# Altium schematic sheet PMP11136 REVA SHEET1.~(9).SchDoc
size 431 x 279 mm; Date: Not shown in title block; ApprovedBy: Not shown in title block; CheckedBy: Not shown in title block; Author: Not shown in title block; CompanyName: Not shown in title block; Engineer: Not shown in title block; Organization: Not shown in title block; Address1: Not shown in title block; Address2: Not shown in title block; Address3: Not shown in title block; Address4: Not shown in title block; DocumentNumber: 1; Revision: Use project parameter SCH_Rev; SheetNumber: 1; SheetTotal: 3; PageSetup: Record=PageOptions¦CenterHorizontal=True¦CenterVertical=True¦PrintScale=1.00¦XCorrection=1.00¦YCorrection=1.00¦PrintKind=0¦BorderSize=5000000¦LeftOffset=0¦BottomOffset=0¦Orientation=2¦PaperLength=1000¦PaperWidth=1000¦Scale=100¦PaperSource=15¦PrintQuality=600¦MediaType=1¦DitherType=10¦PaperKind=Letter¦PrintScaleMode=1
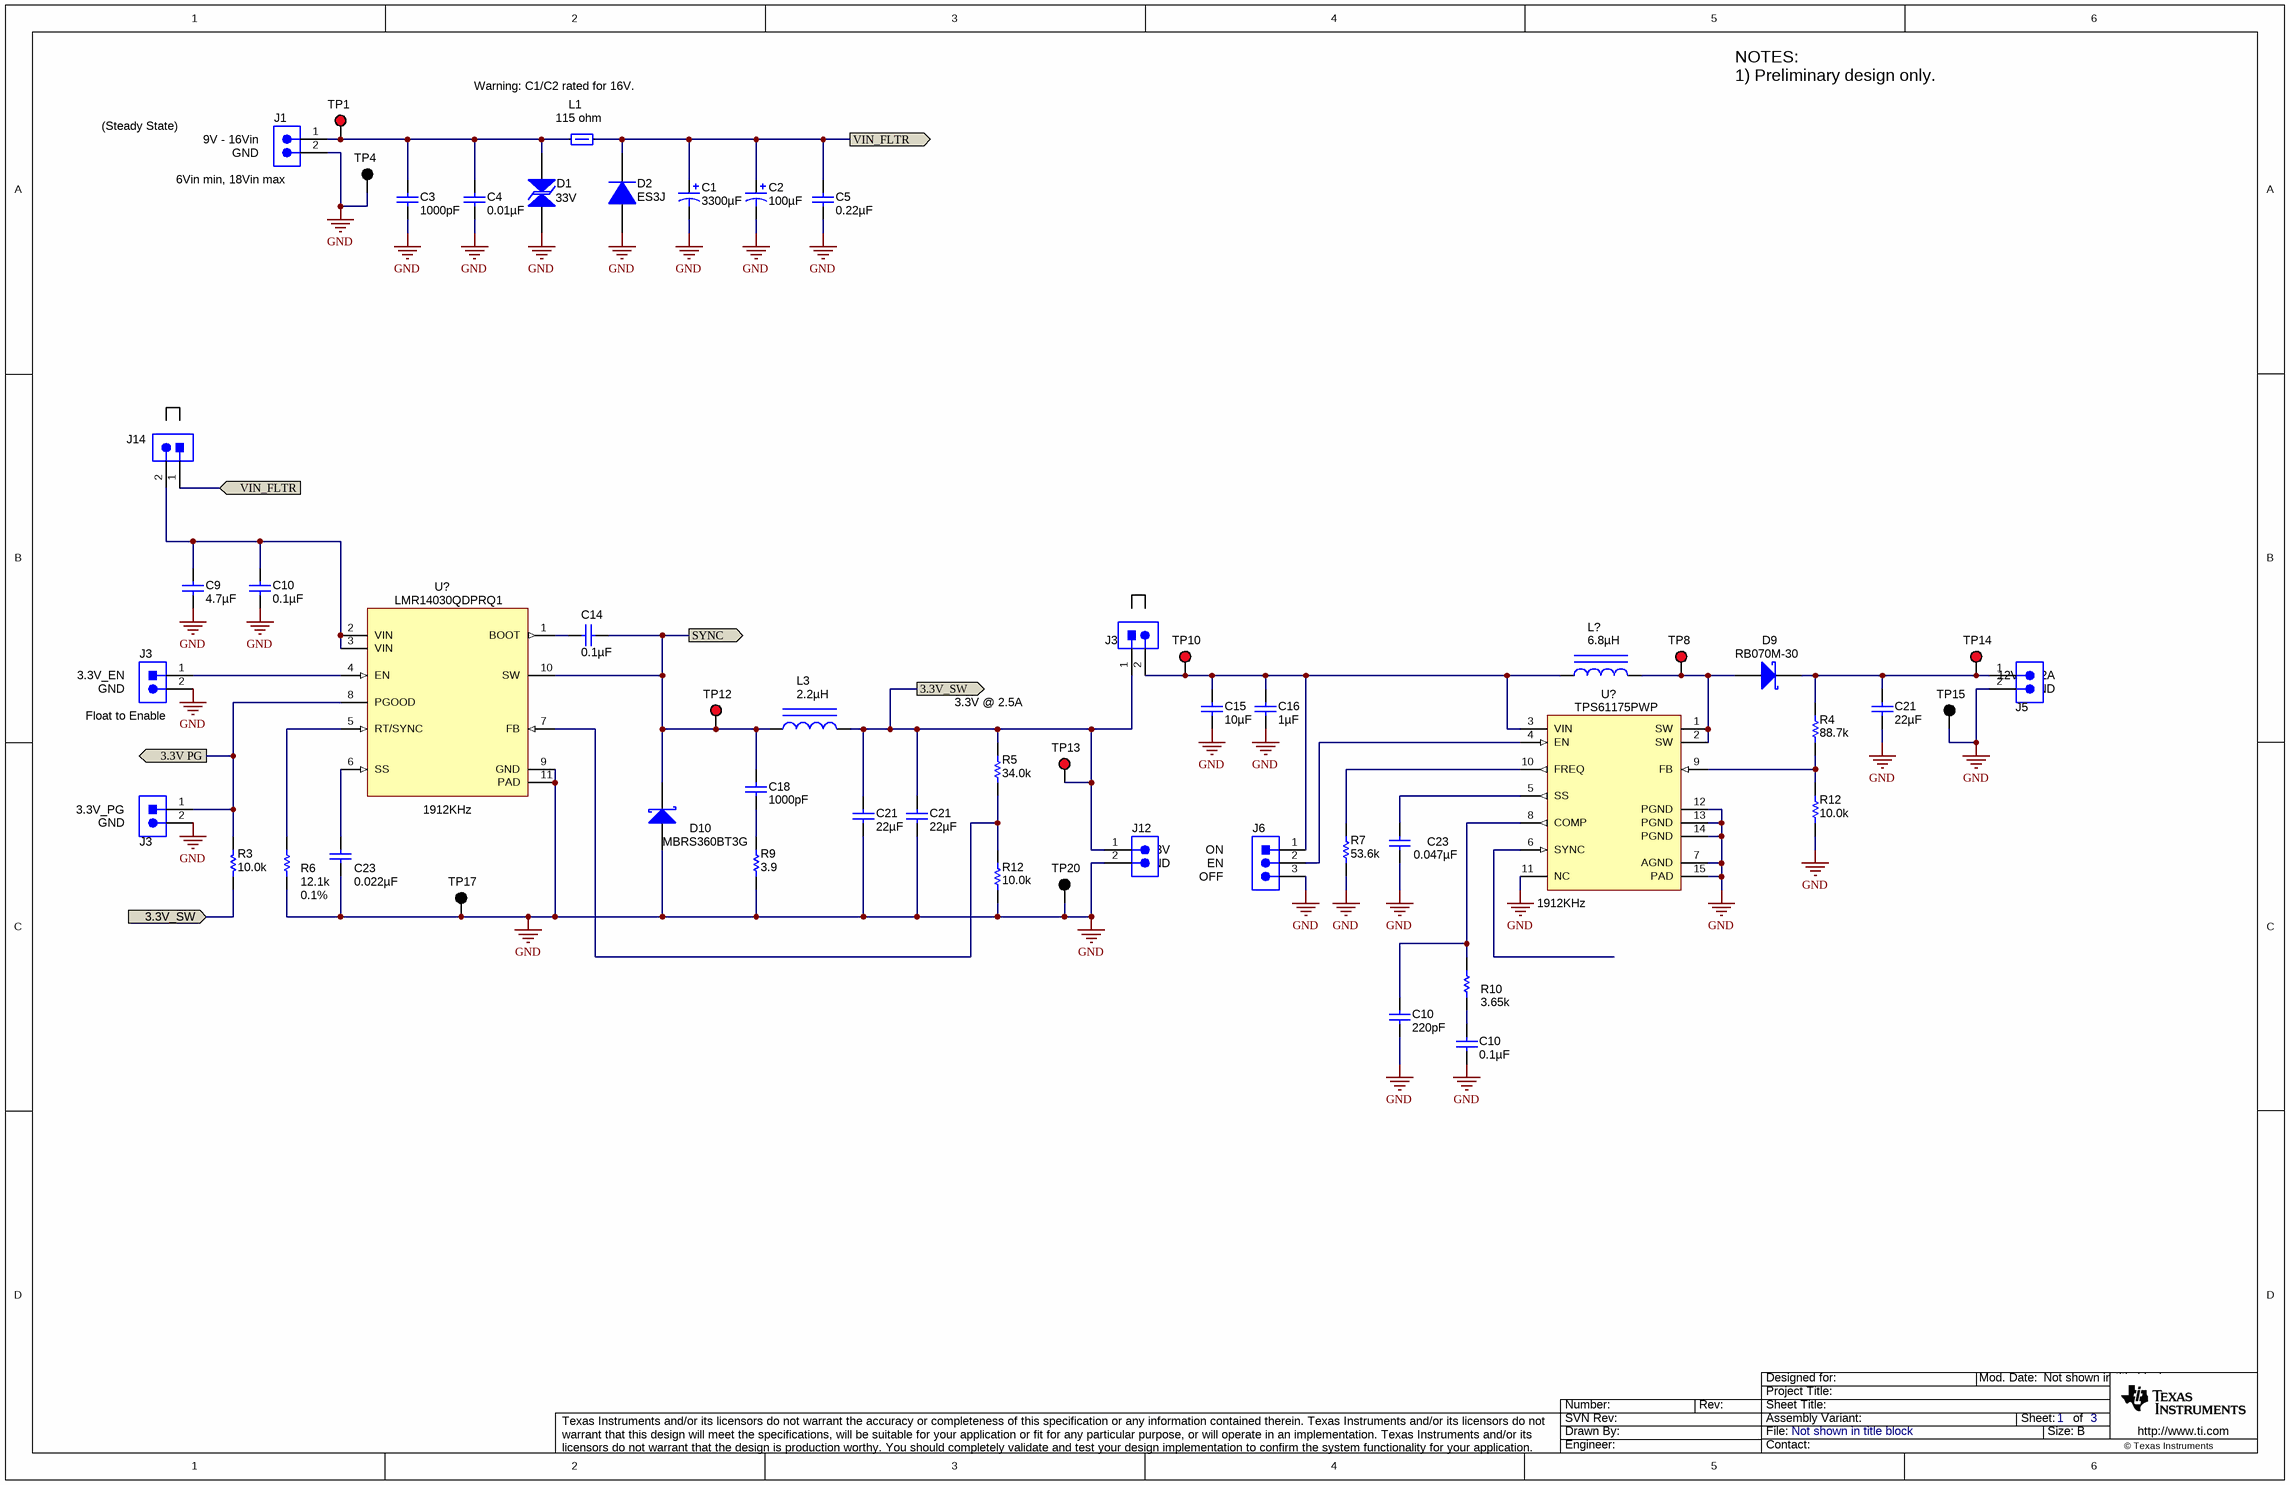
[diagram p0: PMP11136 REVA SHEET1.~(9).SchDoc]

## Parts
(Parts that share a designator on the sheet are numbered #1, #2 ... from top to bottom, then left to right.)
C1  ValueDisplayed: 3300µF  [SM_RADIAL_J16]  (hidden comment: EEV-FK1C332M)
C2  ValueDisplayed: 100µF  [SM_RADIAL_D]  (hidden comment: EEE-FK1C101P)
C3  ValueDisplayed: 1000pF  [0603]  (hidden comment: C1608C0G2A102J)
C4  ValueDisplayed: 0.01µF  [0603]  (hidden comment: C1608X7R2A103K)
C5  ValueDisplayed: 0.22µF  [0603]  (hidden comment: C1608X7R1H224K080AB)
C9  ValueDisplayed: 4.7µF  [1210]  (hidden comment: C3225X7R1H475M250AB)
C10#1  ValueDisplayed: 0.1µF  [0603]  (hidden comment: C1608X7R1H104K)
C10#2  ValueDisplayed: 220pF  [0603]  (hidden comment: C1608X7R1H221K)
C10#3  ValueDisplayed: 0.1µF  [0603]  (hidden comment: C1608X7R1H104K)
C14  ValueDisplayed: 0.1µF  [0603]  (hidden comment: C1608X7R1H104K)
C15  ValueDisplayed: 10µF  [0805]  (hidden comment: GRM21BR71A106KE51L)
C16  ValueDisplayed: 1µF  [0603]  (hidden comment: C1608X7R1E105K)
C18  ValueDisplayed: 1000pF  [0603]  (hidden comment: C1608C0G2A102J)
C21#1  ValueDisplayed: 22µF  [1210]  (hidden comment: C3225X7R1C226M250AC)
C21#2  ValueDisplayed: 22µF  [1210]  (hidden comment: C3225X7R1C226M250AC)
C21#3  ValueDisplayed: 22µF  [1210]  (hidden comment: C3225X7R1C226M250AC)
C23#1  ValueDisplayed: 0.047µF  [0603]  (hidden comment: C1608X7R1H473K)
C23#2  ValueDisplayed: 0.022µF  [0603]  (hidden comment: C1608X7R1H223K)
D1  value 33V  [DO-214AB-Bi]  (hidden comment: 1.5SMC33CA-E3/57T)
D2  ES3J  [SMC]
D9  RB070M-30  [SOD-123]
D10  MBRS360BT3G  [SMB]
J1  ED555/2DS  [TERM_BLK_ED555-2DS]  (value not drawn)
J3#1  PEC02SAAN  [CONN_PEC02SAAN]  (value not drawn)
J3#2  PEC02SAAN  [CONN_PEC02SAAN]  (value not drawn)
J3#3  PEC02SAAN  [CONN_PEC02SAAN]  (value not drawn)
J5  ED555/2DS  [TERM_BLK_ED555-2DS]  (value not drawn)
J6  PEC03SAAN  [CONN_PEC03SAAN]  (value not drawn)
J12  ED555/2DS  [TERM_BLK_ED555-2DS]  (value not drawn)
J14  PEC02SAAN  [CONN_PEC02SAAN]  (value not drawn)
L1  value 115 ohm  [28F0181]  (hidden comment: 28F0181-1SR-10)
L3  ValueDisplayed: 2.2µH  [SDR7045]  (hidden comment: SLF6045T-2R2N3R3-3PF)
L?  ValueDisplayed: 6.8µH  [VLF504015MT]  (hidden comment: VLF504015MT-6R8M)
R3  ValueDisplayed: 10.0k  [0603]  (hidden comment: CRCW060310K0FKEA)
R4  ValueDisplayed: 88.7k  [0603]  (hidden comment: CRCW060388K7FKEA)
R5  ValueDisplayed: 34.0k  [0603]  (hidden comment: CRCW060334K0FKEA)
R6  Value1: 0.1%  ValueDisplayed: 12.1k  [0603]
R7  ValueDisplayed: 53.6k  [0603]  (hidden comment: CRCW060353K6FKEA)
R9  value 3.9  [2010]  (hidden comment: CRCW20103R90JNEF)
R10  ValueDisplayed: 3.65k  [0603]  (hidden comment: CRCW06033K65FKEA)
R12#1  ValueDisplayed: 10.0k  [0603]  (hidden comment: CRCW060310K0FKEA)
R12#2  ValueDisplayed: 10.0k  [0603]  (hidden comment: CRCW060310K0FKEA)
TP1  5000  [Keystone5000]  (value not drawn)
TP4  5001  [Keystone5001]  (value not drawn)
TP8  5000  [Keystone5000]  (value not drawn)
TP10  5000  [Keystone5000]  (value not drawn)
TP12  5000  [Keystone5000]  (value not drawn)
TP13  5000  [Keystone5000]  (value not drawn)
TP14  5000  [Keystone5000]  (value not drawn)
TP15  5001  [Keystone5001]  (value not drawn)
TP17  5001  [Keystone5001]  (value not drawn)
TP20  5001  [Keystone5001]  (value not drawn)
U?#1  LMR14030QDPRQ1  [DPR0010A]
U?#2  TPS61175PWP  [PWP0014E_N]

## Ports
3.3V PG, 3.3V_SW, SYNC, VIN_FLTR

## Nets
GND: C1.2(-) C2.2(-) C3.2 C4.2 C5.2 C9.1 C10#1.2 C10#2.2 C10#3.2 C15.2 C16.2 C21#1.2 C21#2.2 C21#3.2 C23#1.2 C23#2.2 D1.1 D2.2(A) D10.2(A) J1.2 J3#2.2 J3#3.2 J5.2 J6.3 J12.2 R6.1 R7.1 R9.1 R12#1.1 R12#2.1 TP4.1 TP15.1 TP17.1 TP20.1 U?#1.9(GND) U?#1.11(PAD) U?#2.7(AGND) U?#2.11(NC) U?#2.12(PGND) U?#2.13(PGND) U?#2.14(PGND) U?#2.15(PAD)
3.3V PG: J3#3.1 R3.2 U?#1.8(PGOOD) ; port 3.3V PG
3.3V_SW: C21#2.1 C21#3.1 J3#1.1 J12.1 L3.2 R3.1 R5.2 TP13.1 ; port 3.3V_SW
SYNC: C14.2 C18.1 D10.1(K) L3.1 TP12.1 U?#1.10(SW) ; port SYNC
VIN_FLTR: C1.1(+) C2.1(+) C5.1 D2.1(K) J14.1 L1.2 ; port VIN_FLTR
NetC3_1: C3.1 C4.1 D1.2 J1.1 L1.1 TP1.1
NetC9_2: C9.2 C10#1.1 J14.2 U?#1.2(VIN) U?#1.3(VIN)
NetC10#2_1: C10#2.1 R10.2 U?#2.8(COMP)
NetC10#3_1: C10#3.1 R10.1
NetC14_1: C14.1 U?#1.1(BOOT)
NetC15_1: C15.1 C16.1 J3#1.2 J6.1 L?.1 TP10.1 U?#2.3(VIN)
NetC18_2: C18.2 R9.2
NetC21#1_1: C21#1.1 D9.1(K) J5.1 R4.2 TP14.1
NetC23#1_1: C23#1.1 U?#2.5(SS)
NetC23#2_1: C23#2.1 U?#1.6(SS)
NetD9_2: D9.2(A) L?.2 TP8.1 U?#2.1(SW) U?#2.2(SW)
NetJ3#2_1: J3#2.1 U?#1.4(EN)
NetJ6_2: J6.2 U?#2.4(EN)
NetR4_1: R4.1 R12#1.2 U?#2.9(FB)
NetR5_1: R5.1 R12#2.2 U?#1.7(FB)
NetR6_2: R6.2 U?#1.5(RT/SYNC)
NetR7_2: R7.2 U?#2.10(FREQ)

Not connected (* = marked no-connect by the designer): U?#2 6(SYNC)

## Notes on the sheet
- Warning: C1/C2 rated for 16V.
- (near J1) (Steady State)
- (near J1) 9V - 16Vin
- (near J1) GND
- NOTES:
  1) Preliminary design only.
- (near J1) 6Vin min, 18Vin max
- (near J3#2) 3.3V_EN
- (near J3#2) GND
- 3.3V @ 2.5A
- (near J5) 12V@0.2A
- (near J5) GND
- (near J3#2) Float to Enable
- (near J3#3) 3.3V_PG
- (near J3#3) GND
- (near U?#1) 1912KHz
- (near J12) 3.3V
- (near J12) GND
- (near J6) ON
- (near J6) EN
- (near J6) OFF
- (near U?#2) 1912KHz

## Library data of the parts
C1 = EEV-FK1C332M: CAP, AL, 3300 µF, 16 V, +/- 20%, 0.035 ohm, SMD; Manufacturer: Panasonic; Polarized: Y; CompType: Capacitor; Value: 3300uF; U/M: EA; Cap_F: 0.0033; Tolerance_%: 20; VDC_V: 16; Value2: 16V; ESR_ohm: 0.035; IRMS_A: 1.8; TaMin_C: -55; TaMax_C: 105; Cap_Case: J16
C2 = EEE-FK1C101P: CAP, AL, 100 µF, 16 V, +/- 20%, 0.36 ohm, SMD; Manufacturer: Panasonic; Polarized: Y; CompType: Capacitor; Value: 100uF; U/M: EA; Cap_F: 0.0001; Tolerance_%: 20; VDC_V: 16; Value2: 16V; ESR_ohm: 0.36; IRMS_A: 0.24; TaMin_C: -55; TaMax_C: 105; Cap_Case: D
C3 C18 = C1608C0G2A102J: CAP, CERM, 1000 pF, 100 V, +/- 5%, C0G/NP0, 0603; Manufacturer: TDK; Polarized: N; CompType: Capacitor; Value: 1000pF; U/M: EA; Cap_F: 0.000000001; Tolerance_%: 5; ESR_ohm: 0.0589; Value1: 0.0589 ohm; VDC_V: 100; Value2: 100V; TaMin_C: -55; TaMax_C: 125
C4 = C1608X7R2A103K: CAP, CERM, 0.01 µF, 100 V, +/- 10%, X7R, 0603; Manufacturer: TDK; Polarized: N; CompType: Capacitor; Value: 0.01uF; U/M: EA; Cap_F: 0.00000001; Tolerance_%: 10; ESR_ohm: 0.0661; Value1: 0.0661 ohm; VDC_V: 100; Value2: 100V; TaMin_C: -55; TaMax_C: 125
C5 = C1608X7R1H224K080AB: CAP, CERM, 0.22 µF, 50 V, +/- 10%, X7R, 0603; Manufacturer: TDK; Polarized: N; CompType: Capacitor; Value: 0.22uF; U/M: EA; Cap_F: 0.00000022; Tolerance_%: 10; Value1: Unknown; VDC_V: 50; Value2: 50V; TaMin_C: -55; TaMax_C: 125
C9 = C3225X7R1E106M: CAP, CERM, 4.7uF, 50V, +/-20%, X7R, 1210; Manufacturer: TDK; Polarized: N; CompType: Capacitor; U/M: EA; Cap_F: 0.00001; Tolerance_%: 20; ESR_Ohm: 0.0027; Value1: 0.0027 ohm; VDC_V: 50; IRMS_A: 3; TaMin_C: -55; TaMax_C: 125
C10#1 C10#3 C14 = C1608X7R1H104K: CAP, CERM, 0.1uF, 50V, +/-10%, X7R, 0603; Manufacturer: TDK; Polarized: N; CompType: Capacitor; U/M: EA; Cap_F: 0.0000001; Tolerance_%: 10; ESR_Ohm: 0.017; Value1: 0.017 ohm; VDC_V: 50; TaMin_C: -55; TaMax_C: 125
C10#2 = C1608X7R1H221K: CAP, CERM, 220 pF, 50 V, +/- 10%, X7R, 0603; Manufacturer: TDK; Polarized: N; CompType: Capacitor; Value: 220pF; U/M: EA; Cap_F: 0.00000000022; Tolerance_%: 10; Value1: Unknown; VDC_V: 50; Value2: 50V; TaMin_C: -55; TaMax_C: 125
C15 = GRM21BR71A106KE51L: CAP, CERM, 10uF, 10V, +/-10%, X7R, 0805; Manufacturer: MuRata; Polarized: N; CompType: Capacitor; U/M: EA; Cap_F: 0.00001; Tolerance_%: 10; ESR_Ohm: 0.003; Value1: 0.003 ohm; TaMin_C: -55; TaMax_C: 125
C16 = C1608X7R1C105K: CAP, CERM, 1uF, 25V, +/-10%, X7R, 0603; Manufacturer: TDK; Polarized: N; CompType: Capacitor; U/M: EA; Cap_F: 0.000001; Tolerance_%: 10; ESR_Ohm: 0.0057; Value1: 0.0057 ohm; VDC_V: 25; TaMin_C: -55; TaMax_C: 125
C21#1-C21#3 = C3225X7R1C226M: CAP, CERM, 22 µF, 16 V, +/- 20%, X7R, 1210; Manufacturer: TDK; Polarized: N; CompType: Capacitor; Value: 22uF; U/M: EA; Cap_F: 0.000022; Tolerance_%: 20; ESR_ohm: 0.002; Value1: 0.002 ohm; VDC_V: 16; Value2: 16V; IRMS_A: 8.11; TaMin_C: -55; TaMax_C: 125
C23#1 = C1608X7R1H473K: CAP, CERM, 0.047 µF, 50 V, +/- 10%, X7R, 0603; Manufacturer: TDK; Polarized: N; CompType: Capacitor; Value: 0.047uF; U/M: EA; Cap_F: 0.000000047; Tolerance_%: 10; ESR_ohm: 0.0234; Value1: 0.0234 ohm; VDC_V: 50; Value2: 50V; TaMin_C: -55; TaMax_C: 125
C23#2 = C1608X7R1H223K: CAP, CERM, 0.022 µF, 50 V, +/- 10%, X7R, 0603; Manufacturer: TDK; Polarized: N; CompType: Capacitor; Value: 0.022uF; U/M: EA; Cap_F: 0.000000022; Tolerance_%: 10; ESR_ohm: 0.0383; Value1: 0.0383 ohm; VDC_V: 50; Value2: 50V; TaMin_C: -55; TaMax_C: 125
D1 = 1.5SMC33CA-E3/57T: Diode, TVS, Bi, 33V, 1500W, DO-214AB; Manufacturer: Vishay-Dale; U/M: EA; Power_W: 1500; Vr_V: 28.2; RJA_CperW: 75
D2 = ES3D-E3/57T: Diode, Ultrafast, 600V, 3A, SMC; Manufacturer: Fairchild; U/M: EA; Vf_V: 0.9; Value2: 0.9V; Io_A: 3; Vr_V: 600; TJmax_C: 150
D9 = B130LAW-7-F: Diode, Schottky, 30V, 1.5A, SOD-123; Manufacturer: Rohm; U/M: EA; Vf_V: 0.38; Value1: 1A; Value2: 0.38V; Io_A: 1.5; Vr_V: 30; TJmax_C: 125
D10 = MBRS260T3G: Diode, Schottky, 60V, 3A, SMB; Manufacturer: ON Semiconductor; U/M: EA; Vf_V: 0.63; Value2: 0.63V; Io_A: 2; Vr_V: 60; TJmax_C: 125; RJC_CperW: 24
J1 J5 J12 = ED555/2DS: Terminal Block, 6A, 3.5mm Pitch, 2-Pos, TH; Manufacturer: On-Shore Technology, Inc.; SymbolCreator: a0412235; CompType: Connector; U/M: EA
J3#1-J3#3 J14 = PEC02SAAN: Header, 100mil, 2x1, Tin, TH; Manufacturer: Sullins Connector Solutions; SymbolCreator: a0412235; U/M: EA
J6 = PEC03SAAN: Header, 100mil, 3x1, Tin, TH; Manufacturer: Sullins Connector Solutions; SymbolCreator: a0799628; U/M: EA
L1 = 28F0181-1SR-10: Ferrite Bead, 115 ohm @ 100MHz, 10A, SMD, 2-Leads, Body 8.74x4.65mm; Manufacturer: Laird-Signal Integrity Products; Imax_A: 10; DCR_ohm: 0.001; Value1: 0.001 ohm; ZTyp@100MHz_Ohm: 115
L3 = SDR7045-2R2M: Inductor, SMT, 3.3A, 18 milliohm; Manufacturer: TDK; Value: 2.2uH; Ind_H: 2.2E-6; Imax_A: 3.3; DCR_ohm: 0.032; Material: Ferrite
L? = VLF504015MT-6R8M: Inductor, Shielded, Ferrite, 6.8 µH, 1.83 A, 0.08 ohm, SMD; Manufacturer: TDK; Value: 6.8uH; Ind_H: 6.8E-6; Imax_A: 1.83; Irms: 2A @ 40C rise; Isat: 1.83A @ 30% inductance drop; DCR_ohm: 0.08; Value2: 1.83A
R3 R12#1 R12#2 = CRCW060310K0FKEA: RES, 10.0 k, 1%, 0.1 W, 0603; Manufacturer: Vishay-Dale; CompType: Resistor; Value: 10.0k; Res_ohm: 10000; Value_Code: 10k0; Tolerance_%: 1; Power_W: 0.1; Value2: 0.1W; VDC_V: 75; TempCo: 100 ppm/C; EIA_Code: E96; U/M: EA
R4 = CRCW060388K7FKEA: RES, 88.7 k, 1%, 0.1 W, 0603; Manufacturer: Vishay-Dale; CompType: Resistor; Value: 88.7k; Res_ohm: 88700; Value_Code: 88k7; Tolerance_%: 1; Power_W: 0.1; Value2: 0.1W; VDC_V: 75; TempCo: 100 ppm/C; EIA_Code: E96; U/M: EA
R5 = CRCW060334K0FKEA: RES, 34.0 k, 1%, 0.1 W, 0603; Manufacturer: Vishay-Dale; CompType: Resistor; Value: 34.0k; Res_ohm: 34000; Value_Code: 34k0; Tolerance_%: 1; Power_W: 0.1; Value2: 0.1W; VDC_V: 75; TempCo: 100 ppm/C; EIA_Code: E96; U/M: EA
R6 = CRCW060312K1FKEA: RES, 12.1 k, 0.1%, 0.1 W, 0603; Manufacturer: Vishay-Dale; CompType: Resistor; Value: 12.1k; Res_ohm: 12100; Value_Code: 12k1; Tolerance_%: 1; Power_W: 0.1; Value2: 0.1W; VDC_V: 75; TempCo: 100 ppm/C; EIA_Code: E96; U/M: EA
R7 = CRCW060353K6FKEA: RES, 53.6 k, 1%, 0.1 W, 0603; Manufacturer: Vishay-Dale; CompType: Resistor; Value: 53.6k; Res_ohm: 53600; Value_Code: 53k6; Tolerance_%: 1; Power_W: 0.1; Value2: 0.1W; VDC_V: 75; TempCo: 100 ppm/C; EIA_Code: E96; U/M: EA
R9 = CRCW20102R70JNEF: RES, 3.9 ohm, 5%, 0.75W, 2010; Manufacturer: Vishay-Dale; CompType: Resistor; Value_Code: 3R90; Tolerance_%: 5; Power_W: 0.75; VDC_V: 400; TempCo: 200 ppm/C; EIA_Code: E24; U/M: EA
R10 = CRCW06033K65FKEA: RES, 3.65 k, 1%, 0.1 W, 0603; Manufacturer: Vishay-Dale; CompType: Resistor; Value: 3.65k; Res_ohm: 3650; Value_Code: 3k65; Tolerance_%: 1; Power_W: 0.1; Value2: 0.1W; VDC_V: 75; TempCo: 100 ppm/C; EIA_Code: E96; U/M: EA
TP1 TP8 TP10 TP12-TP14 = 5000: Test Point, TH, Miniature, Red; Manufacturer: Keystone; CompType: Test Point Loop; U/M: EA
TP4 TP15 TP17 TP20 = 5001: Test Point, TH, Miniature, Black; Manufacturer: Keystone; CompType: Test Point Loop; U/M: EA
U?#1 = LMR14030QDPRQ1: 40V 3.5A SIMPLE SWITCHER® , 2.2MHz Step-Down Regulator with 40μA Quiescent Current, DPR0010A; Manufacturer: Texas Instruments; SymbolCreator: Altium; CompType: IC; U/M: EA
U?#2 = TPS61175PWP: 3-A High Voltage Boost Converter with Soft-start and Programmable Switching Frequency, PWP0014E; Manufacturer: Texas Instruments; SymbolCreator: a0411947; CompType: IC; U/M: EA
